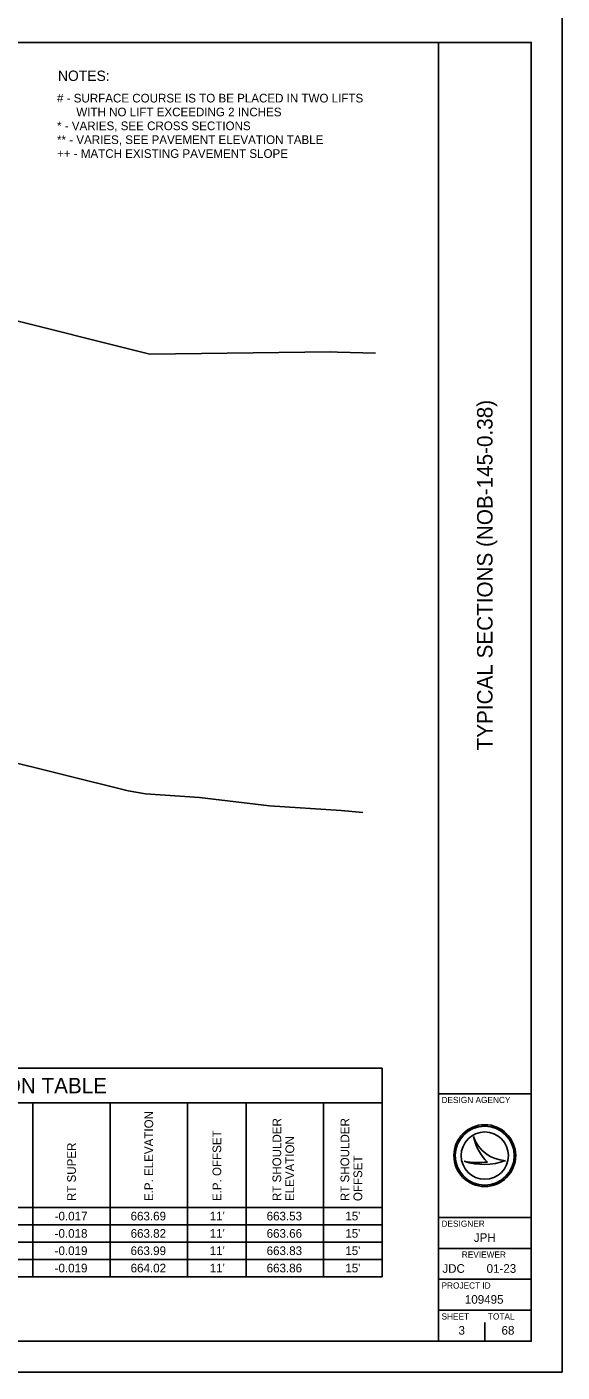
# Model space of a CAD drawing. Extents: x -32 to 102, y -151 to 66.
# Drawn here: x 76 to 102, y -66 to -0.8 of the extents above; entities that cross this region are included whole.
import ezdxf

# ---------------------------------------------------------------- set-up
doc = ezdxf.new("R2010")
doc.units = 0
for name, color, linetype in [('DT_X_Terrain_Ground_Line', 7, 'Continuous'), ('SH_Border', 7, 'Continuous'), ('SH_Cut_Line', 7, 'Continuous'), ('SH_Data', 7, 'Continuous'), ('TX_P_1', 7, 'Continuous'), ('XS_P_Finished_Grade', 7, 'Continuous'), ('XS_X_Ground_Line', 7, 'Continuous')]:
    doc.layers.add(name, color=color, linetype=linetype)

msp = doc.modelspace()

# ---------------------------------------------------------------- linework, layer by layer
at = {"layer": 'DT_X_Terrain_Ground_Line'}
msp.add_lwpolyline([(80.956, -37.812), (81.787, -37.944), (84.416, -38.134), (87.806, -38.536), (91.28, -38.76), (92.339, -38.855)], dxfattribs=at)
at = {"layer": 'SH_Border'}
for p, q in [((96, -64.5), (96, -1.5)), ((96, -52.5), (100.5, -52.5)), ((96, -58.5), (100.5, -58.5)), ((96, -60), (100.5, -60)), ((96, -61.5), (100.5, -61.5)), ((96, -63), (100.5, -63))]:
    msp.add_line(p, q, dxfattribs=at)
msp.add_lwpolyline([(4.5, -1.5), (100.5, -1.5), (100.5, -64.5), (4.5, -64.5)], close=True, dxfattribs=at)
at = {"layer": 'SH_Cut_Line'}
msp.add_lwpolyline([(0, -66), (102, -66), (102, 0), (0, 0)], close=True, dxfattribs=at)
at = {"layer": 'SH_Data'}
for p, q in [((97.702, -54.571), (97.702, -54.571)), ((97.252, -55.771), (97.251, -55.771)), ((98.25, -55.5), (98.25, -55.5)), ((99.262, -55.744), (99.262, -55.744)), ((98.25, -64.5), (98.25, -63.6)), ((97.125, -63.975), (97.125, -63.975))]:
    msp.add_line(p, q, dxfattribs=at)
for radius in [1.5, 1.43, 1.43, 1.147]:
    msp.add_circle((98.25, -55.5), radius, dxfattribs=at)
for centre, radius, start, end in [((99.348, -54.007), 1.74, 198.92567, 198.93195), ((100.04, -54.09), 2.387, 191.63793, 191.64215), ((99.348, -54.007), 1.74, 198.93195, 267.16574), ((100.04, -54.09), 2.387, 191.64215, 226.09467), ((98.218, -52.89), 3.039, 251.45274, 251.45764), ((98.218, -52.89), 3.039, 251.45764, 290.08324), ((97.944, -52.037), 3.798, 259.49639, 259.49952), ((97.944, -52.037), 3.798, 259.49952, 276.66723)]:
    msp.add_arc(centre, radius, start, end, dxfattribs=at)
at = {"layer": 'TX_P_1'}
for p, q in [((51.877, -51.262), (93.277, -51.262)), ((93.277, -51.262), (93.277, -61.373)), ((51.877, -52.942), (93.277, -52.942)), ((76.327, -52.942), (76.327, -61.373)), ((80.077, -52.942), (80.077, -61.373)), ((83.827, -52.942), (83.827, -61.373)), ((86.677, -52.942), (86.677, -61.373)), ((90.427, -52.942), (90.427, -61.373)), ((51.877, -58.013), (93.277, -58.013)), ((51.877, -58.853), (93.277, -58.853)), ((51.877, -59.693), (93.277, -59.693)), ((51.877, -60.533), (93.277, -60.533)), ((51.877, -61.373), (93.277, -61.373))]:
    msp.add_line(p, q, dxfattribs=at)
at = {"layer": 'XS_P_Finished_Grade'}
for p, q in [((69.195, -13.424), (82.007, -16.627)), ((69.195, -34.872), (80.956, -37.812))]:
    msp.add_line(p, q, dxfattribs=at)
at = {"layer": 'XS_X_Ground_Line'}
msp.add_lwpolyline([(82.007, -16.627), (90.771, -16.516), (91.107, -16.521), (92.953, -16.577)], dxfattribs=at)

# ---------------------------------------------------------------- texts
at = {"layer": 'SH_Data'}
msp.add_text('TYPICAL SECTIONS (NOB-145-0.38)', height=0.75, rotation=90, dxfattribs=at).set_placement((98.625, -35.841))
for s, height, p in [('PAVEMENT ELEVATION TABLE', 0.75, (65.043, -52.477)), ('DESIGN AGENCY', 0.3, (96.15, -52.95)), ('DESIGNER', 0.3, (96.15, -58.95)), ('JPH', 0.42, (97.719, -59.685)), ('REVIEWER', 0.3, (97.135, -60.45)), ('JDC', 0.42, (96.191, -61.185)), ('01-23', 0.42, (98.338, -61.185)), ('PROJECT ID', 0.3, (96.15, -61.95)), ('109495', 0.42, (97.283, -62.685)), ('SHEET', 0.3, (96.15, -63.45)), ('TOTAL', 0.3, (98.4, -63.45)), ('3', 0.42, (96.975, -64.185)), ('68', 0.42, (99.062, -64.185))]:
    msp.add_text(s, height=height, dxfattribs=at).set_placement(p)
at = {"layer": 'TX_P_1'}
for s, height, p in [('NOTES:', 0.504, (77.543, -3.372)), ('# - SURFACE COURSE IS TO BE PLACED IN TWO LIFTS', 0.42, (77.498, -4.415)), ('      WITH NO LIFT EXCEEDING 2 INCHES', 0.42, (77.498, -5.087)), ('* - VARIES, SEE CROSS SECTIONS', 0.42, (77.498, -5.759)), ('** - VARIES, SEE PAVEMENT ELEVATION TABLE', 0.42, (77.498, -6.431)), ('++ - MATCH EXISTING PAVEMENT SLOPE', 0.42, (77.498, -7.103)), ('-0.017', 0.42, (77.384, -58.643)), ('663.69', 0.42, (81.068, -58.643)), ("11'", 0.42, (84.905, -58.643)), ('663.53', 0.42, (87.668, -58.643)), ("15'", 0.42, (91.483, -58.643)), ('-0.018', 0.42, (77.383, -59.483)), ('663.82', 0.42, (81.07, -59.483)), ("11'", 0.42, (84.905, -59.483)), ('663.66', 0.42, (87.668, -59.483)), ("15'", 0.42, (91.483, -59.483)), ('-0.019', 0.42, (77.383, -60.323)), ('663.99', 0.42, (81.068, -60.323)), ("11'", 0.42, (84.905, -60.323)), ('663.83', 0.42, (87.668, -60.323)), ("15'", 0.42, (91.483, -60.323)), ('-0.019', 0.42, (77.383, -61.163)), ('664.02', 0.42, (81.07, -61.163)), ("11'", 0.42, (84.905, -61.163)), ('663.86', 0.42, (87.668, -61.163)), ("15'", 0.42, (91.483, -61.163))]:
    msp.add_text(s, height=height, dxfattribs=at).set_placement(p)
for s, p in [('E.P. ELEVATION', (82.162, -57.706)), ('RT SHOULDER', (88.372, -57.706)), ('RT SHOULDER', (91.672, -57.706)), ('E.P. OFFSET', (85.462, -57.706)), ('ELEVATION', (89.002, -57.706)), ('RT SUPER', (78.412, -57.706)), ('OFFSET', (92.302, -57.706))]:
    msp.add_text(s, height=0.42, rotation=90, dxfattribs=at).set_placement(p)

doc.saveas('drawing.dxf')
